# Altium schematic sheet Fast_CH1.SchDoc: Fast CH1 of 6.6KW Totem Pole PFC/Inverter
size A4
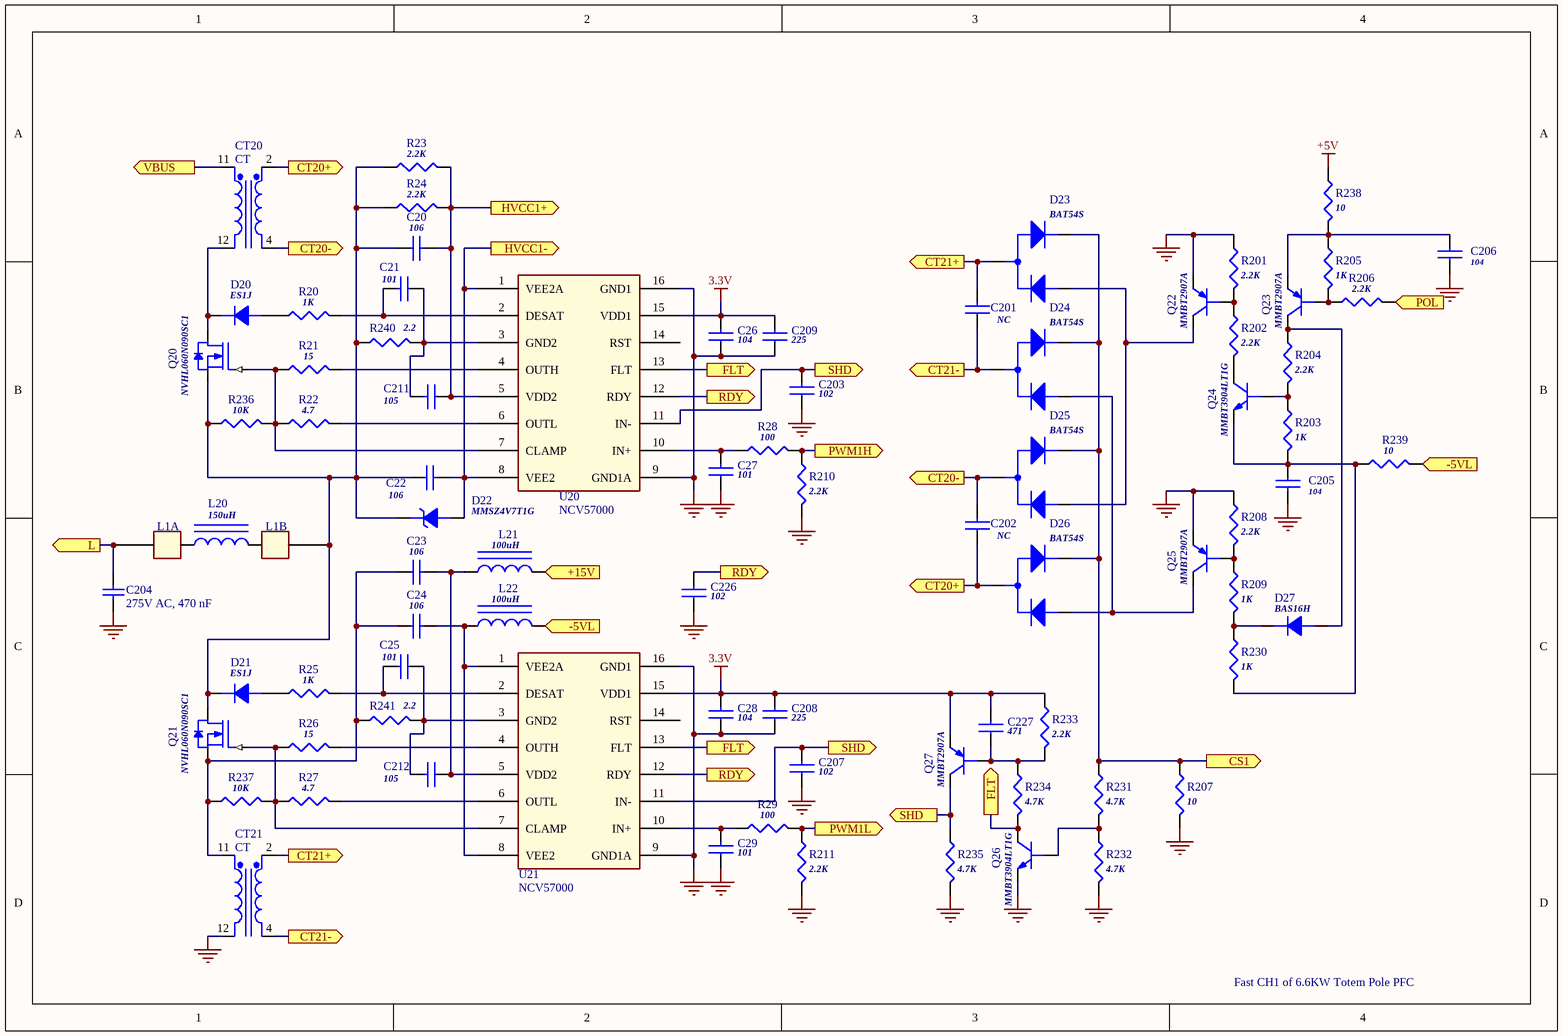
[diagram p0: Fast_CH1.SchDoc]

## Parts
C20  106  [SMT_1206_CM]
C21  101  [SMT_0805_CM]
C22  106  [SMT_1206_CM]
C23  106  [SMT_1206_CM]
C24  106  [SMT_1206_CM]
C25  101  [SMT_0805_CM]
C26  104  [SMT_0805_CM]
C27  101  [SMT_0805_CM]
C28  104  [SMT_0805_CM]
C29  101  [SMT_0805_CM]
C201  NC  [SMT_0805_CM]
C202  NC  [SMT_0805_CM]
C203  102  [SMT_0805_CM]
C204  275V AC, 470 nF  [WCAP-FTX2_18x8x14_CS]
C205  104  [SMT_0805_CM]
C206  104  [SMT_0805_CM]
C207  102  [SMT_0805_CM]
C208  225  [SMT_0805_CM]
C209  225  [SMT_0805_CM]
C211  105  [SMT_0805_CM]
C212  105  [SMT_0805_CM]
C226  102  [SMT_0805_CM]
C227  471  [SMT_0805_CM]
CT20  CT  [CT_EE13]
CT21  CT  [CT_EE13]
D20  ES1J  [DO-214AC(SMA)]
D21  ES1J  [DO-214AC(SMA)]
D22  MMSZ4V7T1G  [SOD-123FL]
D23  BAT54S  [SOT-23-3L]
D24  BAT54S  [SOT-23-3L]
D25  BAT54S  [SOT-23-3L]
D26  BAT54S  [SOT-23-3L]
D27  BAS16H  [SOD-323M]
L1A  (no value)  [TermL]
L1B  (no value)  [TermL]
L20  150uH  [INDUCTOR-7*7*3.5]
L21  100uH  [Bead_1210]
L22  100uH  [Bead_1210]
Q20  NVHL060N090SC1  [TO247]
Q21  NVHL060N090SC1  [TO247]
Q22  MMBT2907A  [SOT-23-3L]
Q23  MMBT2907A  [SOT-23-3L]
Q24  MMBT3904LT1G  [SOT-23-3L]
Q25  MMBT2907A  [SOT-23-3L]
Q26  MMBT3904LT1G  [SOT-23-3L]
Q27  MMBT2907A  [SOT-23-3L]
R20  1K  [SMT_0805_RM]
R21  15  [SMT_1206_RM]
R22  4.7  [SMT_1206_RM]
R23  2.2K  [SMT_1206_RM]
R24  2.2K  [SMT_1206_RM]
R25  1K  [SMT_0805_RM]
R26  15  [SMT_1206_RM]
R27  4.7  [SMT_1206_RM]
R28  100  [SMT_0805_RM]
R29  100  [SMT_0805_RM]
R201  2.2K  [SMT_0805_RM]
R202  2.2K  [SMT_0805_RM]
R203  1K  [SMT_0805_RM]
R204  2.2K  [SMT_0805_RM]
R205  1K  [SMT_0805_RM]
R206  2.2K  [SMT_0805_RM]
R207  10  [SMT_1206_RM]
R208  2.2K  [SMT_0805_RM]
R209  1K  [SMT_0805_RM]
R210  2.2K  [SMT_0805_RM]
R211  2.2K  [SMT_0805_RM]
R230  1K  [SMT_1206_RM]
R231  4.7K  [SMT_0805_RM]
R232  4.7K  [SMT_0805_RM]
R233  2.2K  [SMT_0805_RM]
R234  4.7K  [SMT_0805_RM]
R235  4.7K  [SMT_0805_RM]
R236  10K  [SMT_0805_RM]
R237  10K  [SMT_0805_RM]
R238  10  [SMT_0805_RM]
R239  10  [SMT_0805_RM]
R240  2.2  [SMT_0805_RM]
R241  2.2  [SMT_0805_RM]
U20  NCV57000  [SOP16W]
U21  NCV57000  [SOP16W]

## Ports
+15V (out), -5VL (out), CS1 (out), CT20+ (out), CT20- (out), CT21+ (out), CT21- (out), FLT (out), HVCC1+ (out), HVCC1- (out), L (out), POL (out), PWM1H (out), PWM1L (out), RDY (out), SHD (out), VBUS (out)

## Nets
3.3V: C26.2 C28.2 C208.2 C209.2 C227.2 Q27.2(E) R233.1 U20.15(VDD1) U21.15(VDD1)
+5V: R238.1
PGND: C26.1 C27.1 C28.1 C29.1 C203.1 C204.2 C205.2 C206.2 C207.1 C208.1 C209.1 C226.1 CT21.12(Pri-) Q22.2(E) Q25.2(E) Q26.2(E) R201.1 R207.2 R208.1 R210.2 R211.2 R232.2 R235.2 U20.9(GND1A) U20.16(GND1) U21.9(GND1A) U21.16(GND1)
+15V: L21.2 ; port +15V
-5VL: L22.2 R239.2 ; port -5VL
CS1: D23.2 D24.2 D25.2 D26.2 R207.1 R231.1 ; port CS1
CT20+: C202.1 CT20.2(Sec+) D26.3 ; port CT20+
CT20-: C202.2 CT20.4(Sec-) D25.3 ; port CT20-
CT21+: C201.2 CT21.2(Sec+) D23.3 ; port CT21+
CT21-: C201.1 CT21.4(Sec-) D24.3 ; port CT21-
FLT: Q26.3(C) R234.2 U20.13(FLT) U21.13(FLT) ; port FLT
HVCC1+: C20.2 C211.1 R23.2 R24.2 U20.5(VDD2) ; port HVCC1+
HVCC1-: C22.2 D22.1(ANODE) U20.1(VEE2A) U20.8(VEE2) ; port HVCC1-
L: C204.1 L1A.1 ; port L
POL: R206.2 ; port POL
PWM1H: R28.2 R210.1 ; port PWM1H
PWM1L: R29.2 R211.1 ; port PWM1L
RDY: C226.2 U20.12(RDY) U21.12(RDY) ; port RDY
SHD: C203.2 C207.2 Q27.3(C) R235.1 U20.11(IN-) U21.11(IN-) ; port SHD
VBUS: CT20.11(Pri+) ; port VBUS
NetC20_1: C20.1 C22.1 D21.2(K) D22.2(CATHODE) L1B.1 Q20.3(SOURCE) Q21.2(DRAIN) R23.1 R24.1 R236.1 R240.1
NetC21_1: C21.1 C211.2 R240.2 U20.3(GND2)
NetC21_2: C21.2 R20.2 U20.2(DESAT)
NetC23_1: C23.1 C24.1 CT21.11(Pri+) Q21.3(SOURCE) R237.1 R241.1
NetC23_2: C23.2 C212.1 L21.1 U21.5(VDD2)
NetC24_2: C24.2 L22.1 U21.1(VEE2A) U21.8(VEE2)
NetC25_1: C25.1 C212.2 R241.2 U21.3(GND2)
NetC25_2: C25.2 R25.2 U21.2(DESAT)
NetC27_2: C27.2 R28.1 U20.10(IN+)
NetC29_2: C29.2 R29.1 U21.10(IN+)
NetC205_1: C205.1 Q24.2(E) R203.2 R230.2 R239.1
NetC206_1: C206.1 Q23.2(E) R205.1 R238.2
NetC227_1: C227.1 Q27.1(B) R233.2 R234.1
NetCT20_12: CT20.12(Pri-) D20.2(K) Q20.2(DRAIN)
NetD20_1: D20.1(A) R20.1
NetD21_1: D21.1(A) R25.1
NetD23_1: D23.1 D25.1 Q22.3(C)
NetD24_1: D24.1 D26.1 Q25.3(C)
NetD27_1: D27.1(A) Q23.3(C) R204.1
NetD27_2: D27.2(K) R209.2 R230.1
NetQ20_1: Q20.1(GATE) R21.1 R22.1 R236.2 U20.7(CLAMP)
NetQ21_1: Q21.1(GATE) R26.1 R27.1 R237.2 U21.7(CLAMP)
NetQ22_1: Q22.1(B) R201.2 R202.1
NetQ23_1: Q23.1(B) R205.2 R206.1
NetQ24_1: Q24.1(B) R203.1 R204.2
NetQ24_3: Q24.3(C) R202.2
NetQ25_1: Q25.1(B) R208.2 R209.1
NetQ26_1: Q26.1(B) R231.2 R232.1
NetR21_2: R21.2 U20.4(OUTH)
NetR22_2: R22.2 U20.6(OUTL)
NetR26_2: R26.2 U21.4(OUTH)
NetR27_2: R27.2 U21.6(OUTL)

Not connected (* = marked no-connect by the designer): L20 1 2; U20 14(RST); U21 14(RST)

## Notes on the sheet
- Fast CH1 of 6.6KW Totem Pole PFC

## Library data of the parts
C20-C25 C201 C202 = CAP_1206
C26-C29 C203 C207-C209 C211 C212 C226 C227 = CAP_0805
C204 = 890324025039CS: WCAP-FTX2 Film Capacitors, 18x8x14mm, 275V AC, 470 nF; Rated Voltage: 275V AC; Value: 470 nF
C205 C206 = CAP NP
CT20 CT21 = Trans Cupl: Transformer (Coupled Inductor Model)
D20 D21 = D_SMA(DO-214AC)
D22 = DIODE ZENER
D23-D26 = BAT54S/SOT
D27 = DIODE
L1A L1B = P_1
L20-L22 = INDUCTOR IRON
Q20 Q21 = SICMOS
Q22 Q23 Q25 Q27 = Q_PNP_SOT-23-3L
Q24 Q26 = Q_NPN_SOT-23-3L
R20-R29 R206 R236 R237 R239-R241 = R_0805
R201-R205 R207-R211 R230-R235 R238 = R
U20 U21 = U_NCV57000_SO-16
